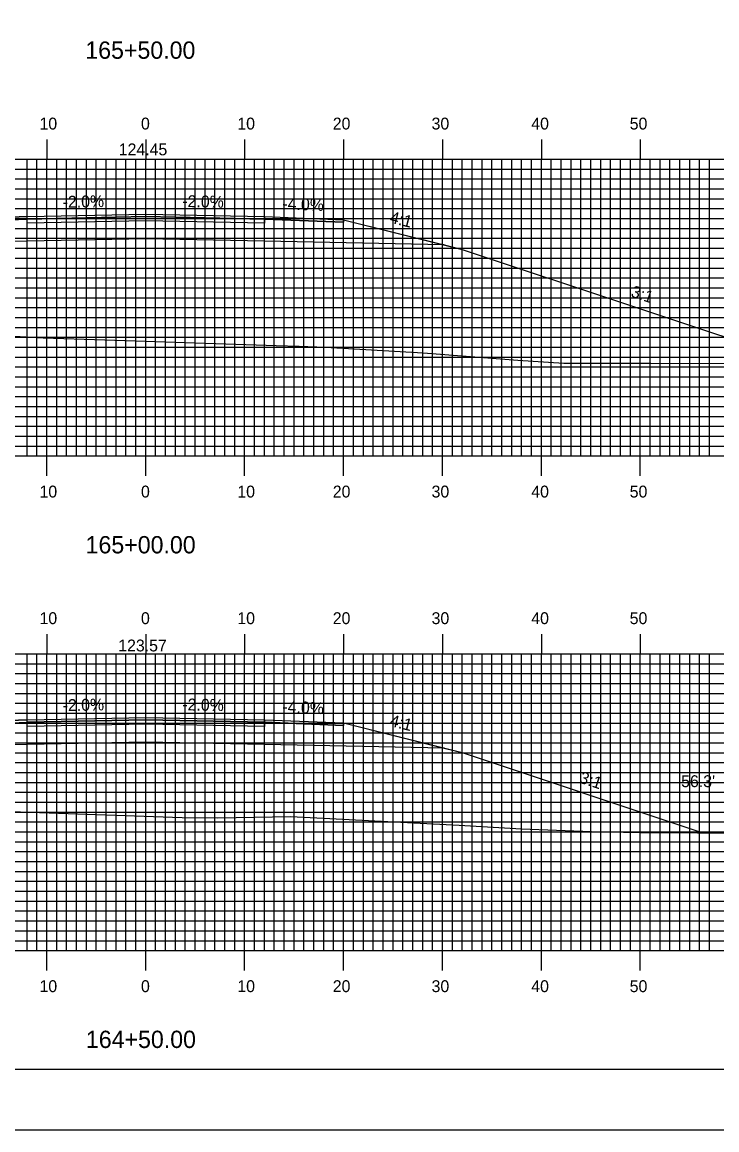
# Model space of a CAD drawing. Extents: x 1781073 to 1781416, y 442591 to 442811.
# Drawn here: x 1781226.4 to 1781296.6, y 442590.5 to 442702.5 of the extents above; entities that cross this region are included whole.
import ezdxf

# ---------------------------------------------------------------- set-up
doc = ezdxf.new("R2010")
doc.units = 0
for name, color, linetype in [('ANNOTATION', 7, 'Continuous'), ('BORDER', 7, 'Continuous'), ('D_Roadway_Centerline', 7, 'Continuous'), ('D_Roadway_Centerline_Text', 7, 'Continuous'), ('D_Roadway_Edge_Shoulder', 7, 'Continuous'), ('D_Roadway_Edge_TW', 7, 'Continuous'), ('D_Roadway_Pavement', 7, 'Continuous'), ('D_Roadway_SlopeLines', 7, 'Continuous'), ('D_Roadway_SubGrade', 7, 'Continuous'), ('D_Text_Standard', 7, 'Continuous'), ('H_V ANNOTATION', 7, 'Continuous'), ('MAJOR', 7, 'Continuous'), ('MINOR', 7, 'Continuous'), ('PLOT BOUNDARY', 7, 'Continuous'), ('S_Roadway_Centerline', 7, 'Continuous')]:
    doc.layers.add(name, color=color, linetype=linetype)

msp = doc.modelspace()

# ---------------------------------------------------------------- linework, layer by layer
at = {"layer": 'BORDER'}
msp.add_lwpolyline([(1781089.29, 442596.67), (1781409.29, 442596.67), (1781409.29, 442806.67), (1781089.29, 442806.67)], close=True, dxfattribs=at)
at = {"layer": 'D_Roadway_Centerline'}
for points in [[(1781185.99, 442672.58), (1781206.89, 442679.55), (1781208.72, 442680.01), (1781218.89, 442682.55), (1781226.89, 442682.87), (1781238.89, 442683.11), (1781250.89, 442682.87), (1781258.89, 442682.55), (1781269.07, 442680.01), (1781270.89, 442679.55), (1781305.63, 442667.98)], [(1781190.49, 442624.58), (1781206.89, 442628.68), (1781208.72, 442629.13), (1781218.89, 442631.68), (1781226.89, 442632), (1781238.89, 442632.24), (1781250.89, 442632), (1781258.89, 442631.68), (1781269.07, 442629.13), (1781270.89, 442628.68), (1781295.21, 442620.57)]]:
    msp.add_lwpolyline(points, dxfattribs=at)
at = {"layer": 'D_Roadway_Edge_Shoulder'}
for points in [[(1781226.89, 442682.87), (1781218.89, 442682.55), (1781218.89, 442682.3), (1781226.89, 442682.62)], [(1781250.89, 442682.87), (1781258.89, 442682.55), (1781258.89, 442682.3), (1781250.89, 442682.62)], [(1781226.89, 442632), (1781218.89, 442631.68), (1781218.89, 442631.43), (1781226.89, 442631.75)], [(1781250.89, 442632), (1781258.89, 442631.68), (1781258.89, 442631.43), (1781250.89, 442631.75)]]:
    msp.add_lwpolyline(points, close=True, dxfattribs=at)
at = {"layer": 'D_Roadway_Edge_TW'}
for points in [[(1781226.89, 442682.62), (1781226.89, 442682.87), (1781238.89, 442683.11), (1781250.89, 442682.87), (1781250.89, 442682.62), (1781238.89, 442682.86)], [(1781226.89, 442631.75), (1781226.89, 442632), (1781238.89, 442632.24), (1781250.89, 442632), (1781250.89, 442631.75), (1781238.89, 442631.99)]]:
    msp.add_lwpolyline(points, close=True, dxfattribs=at)
at = {"layer": 'D_Roadway_Pavement'}
for points in [[(1781226.89, 442682.21), (1781226.89, 442682.62), (1781238.89, 442682.86), (1781250.89, 442682.62), (1781250.89, 442682.21), (1781238.89, 442682.45)], [(1781226.89, 442631.33), (1781226.89, 442631.75), (1781238.89, 442631.99), (1781250.89, 442631.75), (1781250.89, 442631.33), (1781238.89, 442631.57)]]:
    msp.add_lwpolyline(points, close=True, dxfattribs=at)
at = {"layer": 'D_Roadway_SlopeLines'}
for points in [[(1781258.89, 442682.55), (1781270.89, 442679.55), (1781305.63, 442667.98)], [(1781258.89, 442631.68), (1781270.89, 442628.68), (1781295.21, 442620.57)]]:
    msp.add_lwpolyline(points, dxfattribs=at)
at = {"layer": 'D_Roadway_SubGrade'}
for points in [[(1781226.89, 442680.37), (1781208.72, 442680.01), (1781218.89, 442682.55), (1781218.89, 442682.3), (1781226.89, 442682.62), (1781238.89, 442682.86), (1781250.89, 442682.62), (1781258.89, 442682.3), (1781258.89, 442682.55), (1781269.07, 442680.01), (1781250.89, 442680.37), (1781238.89, 442680.61)], [(1781226.89, 442629.5), (1781208.72, 442629.13), (1781218.89, 442631.68), (1781218.89, 442631.43), (1781226.89, 442631.75), (1781238.89, 442631.99), (1781250.89, 442631.75), (1781258.89, 442631.43), (1781258.89, 442631.68), (1781269.07, 442629.13), (1781250.89, 442629.5), (1781238.89, 442629.74)]]:
    msp.add_lwpolyline(points, close=True, dxfattribs=at)
at = {"layer": 'MAJOR'}
for p, q in [((1781228.89, 442690.67), (1781228.89, 442688.67)), ((1781238.89, 442690.67), (1781238.89, 442688.67)), ((1781248.89, 442690.67), (1781248.89, 442688.67)), ((1781258.89, 442690.67), (1781258.89, 442688.67)), ((1781268.89, 442690.67), (1781268.89, 442688.67)), ((1781278.89, 442690.67), (1781278.89, 442688.67)), ((1781288.89, 442690.67), (1781288.89, 442688.67)), ((1781098.89, 442688.67), (1781378.89, 442688.67)), ((1781098.89, 442688.67), (1781378.89, 442688.67)), ((1781228.89, 442658.67), (1781228.89, 442688.67)), ((1781238.89, 442658.67), (1781238.89, 442688.67)), ((1781248.89, 442658.67), (1781248.89, 442688.67)), ((1781258.89, 442658.67), (1781258.89, 442688.67)), ((1781268.89, 442658.67), (1781268.89, 442688.67)), ((1781278.89, 442658.67), (1781278.89, 442688.67)), ((1781288.89, 442658.67), (1781288.89, 442688.67)), ((1781098.89, 442683.67), (1781378.89, 442683.67)), ((1781098.89, 442678.67), (1781378.89, 442678.67)), ((1781098.89, 442673.67), (1781378.89, 442673.67)), ((1781098.89, 442668.67), (1781378.89, 442668.67)), ((1781098.89, 442663.67), (1781378.89, 442663.67)), ((1781098.89, 442658.67), (1781378.89, 442658.67)), ((1781098.89, 442658.67), (1781378.89, 442658.67)), ((1781228.89, 442656.66), (1781228.89, 442658.67)), ((1781238.89, 442656.66), (1781238.89, 442658.67)), ((1781248.89, 442656.66), (1781248.89, 442658.67)), ((1781258.89, 442656.66), (1781258.89, 442658.67)), ((1781268.89, 442656.66), (1781268.89, 442658.67)), ((1781278.89, 442656.66), (1781278.89, 442658.67)), ((1781288.89, 442656.66), (1781288.89, 442658.67)), ((1781228.89, 442640.67), (1781228.89, 442638.67)), ((1781238.89, 442640.67), (1781238.89, 442638.67)), ((1781248.89, 442640.67), (1781248.89, 442638.67)), ((1781258.89, 442640.67), (1781258.89, 442638.67)), ((1781268.89, 442640.67), (1781268.89, 442638.67)), ((1781278.89, 442640.67), (1781278.89, 442638.67)), ((1781288.89, 442640.67), (1781288.89, 442638.67)), ((1781098.89, 442638.67), (1781378.89, 442638.67)), ((1781098.89, 442638.67), (1781378.89, 442638.67)), ((1781228.89, 442608.67), (1781228.89, 442638.67)), ((1781238.89, 442608.67), (1781238.89, 442638.67)), ((1781248.89, 442608.67), (1781248.89, 442638.67)), ((1781258.89, 442608.67), (1781258.89, 442638.67)), ((1781268.89, 442608.67), (1781268.89, 442638.67)), ((1781278.89, 442608.67), (1781278.89, 442638.67)), ((1781288.89, 442608.67), (1781288.89, 442638.67)), ((1781098.89, 442633.67), (1781378.89, 442633.67)), ((1781098.89, 442628.67), (1781378.89, 442628.67)), ((1781098.89, 442623.67), (1781378.89, 442623.67)), ((1781098.89, 442618.67), (1781378.89, 442618.67)), ((1781098.89, 442613.67), (1781378.89, 442613.67)), ((1781098.89, 442608.67), (1781378.89, 442608.67)), ((1781098.89, 442608.67), (1781378.89, 442608.67)), ((1781228.89, 442606.66), (1781228.89, 442608.67)), ((1781238.89, 442606.66), (1781238.89, 442608.67)), ((1781248.89, 442606.66), (1781248.89, 442608.67)), ((1781258.89, 442606.66), (1781258.89, 442608.67)), ((1781268.89, 442606.66), (1781268.89, 442608.67)), ((1781278.89, 442606.66), (1781278.89, 442608.67)), ((1781288.89, 442606.66), (1781288.89, 442608.67))]:
    msp.add_line(p, q, dxfattribs=at)
at = {"layer": 'MINOR'}
for p, q in [((1781226.89, 442658.67), (1781226.89, 442688.67)), ((1781227.89, 442658.67), (1781227.89, 442688.67)), ((1781229.89, 442658.67), (1781229.89, 442688.67)), ((1781230.89, 442658.67), (1781230.89, 442688.67)), ((1781231.89, 442658.67), (1781231.89, 442688.67)), ((1781232.89, 442658.67), (1781232.89, 442688.67)), ((1781233.89, 442658.67), (1781233.89, 442688.67)), ((1781234.89, 442658.67), (1781234.89, 442688.67)), ((1781235.89, 442658.67), (1781235.89, 442688.67)), ((1781236.89, 442658.67), (1781236.89, 442688.67)), ((1781237.89, 442658.67), (1781237.89, 442688.67)), ((1781239.89, 442658.67), (1781239.89, 442688.67)), ((1781240.89, 442658.67), (1781240.89, 442688.67)), ((1781241.89, 442658.67), (1781241.89, 442688.67)), ((1781242.89, 442658.67), (1781242.89, 442688.67)), ((1781243.89, 442658.67), (1781243.89, 442688.67)), ((1781244.89, 442658.67), (1781244.89, 442688.67)), ((1781245.89, 442658.67), (1781245.89, 442688.67)), ((1781246.89, 442658.67), (1781246.89, 442688.67)), ((1781247.89, 442658.67), (1781247.89, 442688.67)), ((1781249.89, 442658.67), (1781249.89, 442688.67)), ((1781250.89, 442658.67), (1781250.89, 442688.67)), ((1781251.89, 442658.67), (1781251.89, 442688.67)), ((1781252.89, 442658.67), (1781252.89, 442688.67)), ((1781253.89, 442658.67), (1781253.89, 442688.67)), ((1781254.89, 442658.67), (1781254.89, 442688.67)), ((1781255.89, 442658.67), (1781255.89, 442688.67)), ((1781256.89, 442658.67), (1781256.89, 442688.67)), ((1781257.89, 442658.67), (1781257.89, 442688.67)), ((1781259.89, 442658.67), (1781259.89, 442688.67)), ((1781260.89, 442658.67), (1781260.89, 442688.67)), ((1781261.89, 442658.67), (1781261.89, 442688.67)), ((1781262.89, 442658.67), (1781262.89, 442688.67)), ((1781263.89, 442658.67), (1781263.89, 442688.67)), ((1781264.89, 442658.67), (1781264.89, 442688.67)), ((1781265.89, 442658.67), (1781265.89, 442688.67)), ((1781266.89, 442658.67), (1781266.89, 442688.67)), ((1781267.89, 442658.67), (1781267.89, 442688.67)), ((1781269.89, 442658.67), (1781269.89, 442688.67)), ((1781270.89, 442658.67), (1781270.89, 442688.67)), ((1781271.89, 442658.67), (1781271.89, 442688.67)), ((1781272.89, 442658.67), (1781272.89, 442688.67)), ((1781273.89, 442658.67), (1781273.89, 442688.67)), ((1781274.89, 442658.67), (1781274.89, 442688.67)), ((1781275.89, 442658.67), (1781275.89, 442688.67)), ((1781276.89, 442658.67), (1781276.89, 442688.67)), ((1781277.89, 442658.67), (1781277.89, 442688.67)), ((1781279.89, 442658.67), (1781279.89, 442688.67)), ((1781280.89, 442658.67), (1781280.89, 442688.67)), ((1781281.89, 442658.67), (1781281.89, 442688.67)), ((1781282.89, 442658.67), (1781282.89, 442688.67)), ((1781283.89, 442658.67), (1781283.89, 442688.67)), ((1781284.89, 442658.67), (1781284.89, 442688.67)), ((1781285.89, 442658.67), (1781285.89, 442688.67)), ((1781286.89, 442658.67), (1781286.89, 442688.67)), ((1781287.89, 442658.67), (1781287.89, 442688.67)), ((1781289.89, 442658.67), (1781289.89, 442688.67)), ((1781290.89, 442658.67), (1781290.89, 442688.67)), ((1781291.89, 442658.67), (1781291.89, 442688.67)), ((1781292.89, 442658.67), (1781292.89, 442688.67)), ((1781293.89, 442658.67), (1781293.89, 442688.67)), ((1781294.89, 442658.67), (1781294.89, 442688.67)), ((1781295.89, 442658.67), (1781295.89, 442688.67)), ((1781098.89, 442687.67), (1781378.89, 442687.67)), ((1781098.89, 442686.67), (1781378.89, 442686.67)), ((1781098.89, 442685.67), (1781378.89, 442685.67)), ((1781098.89, 442684.67), (1781378.89, 442684.67)), ((1781098.89, 442682.67), (1781378.89, 442682.67)), ((1781098.89, 442681.67), (1781378.89, 442681.67)), ((1781098.89, 442680.67), (1781378.89, 442680.67)), ((1781098.89, 442679.67), (1781378.89, 442679.67)), ((1781098.89, 442677.67), (1781378.89, 442677.67)), ((1781098.89, 442676.67), (1781378.89, 442676.67)), ((1781098.89, 442675.67), (1781378.89, 442675.67)), ((1781098.89, 442674.67), (1781378.89, 442674.67)), ((1781098.89, 442672.67), (1781378.89, 442672.67)), ((1781098.89, 442671.67), (1781378.89, 442671.67)), ((1781098.89, 442670.67), (1781378.89, 442670.67)), ((1781098.89, 442669.67), (1781378.89, 442669.67)), ((1781098.89, 442667.67), (1781378.89, 442667.67)), ((1781098.89, 442666.67), (1781378.89, 442666.67)), ((1781098.89, 442665.67), (1781378.89, 442665.67)), ((1781098.89, 442664.67), (1781378.89, 442664.67)), ((1781098.89, 442662.67), (1781378.89, 442662.67)), ((1781098.89, 442661.67), (1781378.89, 442661.67)), ((1781098.89, 442660.67), (1781378.89, 442660.67)), ((1781098.89, 442659.67), (1781378.89, 442659.67)), ((1781226.89, 442608.67), (1781226.89, 442638.67)), ((1781227.89, 442608.67), (1781227.89, 442638.67)), ((1781229.89, 442608.67), (1781229.89, 442638.67)), ((1781230.89, 442608.67), (1781230.89, 442638.67)), ((1781231.89, 442608.67), (1781231.89, 442638.67)), ((1781232.89, 442608.67), (1781232.89, 442638.67)), ((1781233.89, 442608.67), (1781233.89, 442638.67)), ((1781234.89, 442608.67), (1781234.89, 442638.67)), ((1781235.89, 442608.67), (1781235.89, 442638.67)), ((1781236.89, 442608.67), (1781236.89, 442638.67)), ((1781237.89, 442608.67), (1781237.89, 442638.67)), ((1781239.89, 442608.67), (1781239.89, 442638.67)), ((1781240.89, 442608.67), (1781240.89, 442638.67)), ((1781241.89, 442608.67), (1781241.89, 442638.67)), ((1781242.89, 442608.67), (1781242.89, 442638.67)), ((1781243.89, 442608.67), (1781243.89, 442638.67)), ((1781244.89, 442608.67), (1781244.89, 442638.67)), ((1781245.89, 442608.67), (1781245.89, 442638.67)), ((1781246.89, 442608.67), (1781246.89, 442638.67)), ((1781247.89, 442608.67), (1781247.89, 442638.67)), ((1781249.89, 442608.67), (1781249.89, 442638.67)), ((1781250.89, 442608.67), (1781250.89, 442638.67)), ((1781251.89, 442608.67), (1781251.89, 442638.67)), ((1781252.89, 442608.67), (1781252.89, 442638.67)), ((1781253.89, 442608.67), (1781253.89, 442638.67)), ((1781254.89, 442608.67), (1781254.89, 442638.67)), ((1781255.89, 442608.67), (1781255.89, 442638.67)), ((1781256.89, 442608.67), (1781256.89, 442638.67)), ((1781257.89, 442608.67), (1781257.89, 442638.67)), ((1781259.89, 442608.67), (1781259.89, 442638.67)), ((1781260.89, 442608.67), (1781260.89, 442638.67)), ((1781261.89, 442608.67), (1781261.89, 442638.67)), ((1781262.89, 442608.67), (1781262.89, 442638.67)), ((1781263.89, 442608.67), (1781263.89, 442638.67)), ((1781264.89, 442608.67), (1781264.89, 442638.67)), ((1781265.89, 442608.67), (1781265.89, 442638.67)), ((1781266.89, 442608.67), (1781266.89, 442638.67)), ((1781267.89, 442608.67), (1781267.89, 442638.67)), ((1781269.89, 442608.67), (1781269.89, 442638.67)), ((1781270.89, 442608.67), (1781270.89, 442638.67)), ((1781271.89, 442608.67), (1781271.89, 442638.67)), ((1781272.89, 442608.67), (1781272.89, 442638.67)), ((1781273.89, 442608.67), (1781273.89, 442638.67)), ((1781274.89, 442608.67), (1781274.89, 442638.67)), ((1781275.89, 442608.67), (1781275.89, 442638.67)), ((1781276.89, 442608.67), (1781276.89, 442638.67)), ((1781277.89, 442608.67), (1781277.89, 442638.67)), ((1781279.89, 442608.67), (1781279.89, 442638.67)), ((1781280.89, 442608.67), (1781280.89, 442638.67)), ((1781281.89, 442608.67), (1781281.89, 442638.67)), ((1781282.89, 442608.67), (1781282.89, 442638.67)), ((1781283.89, 442608.67), (1781283.89, 442638.67)), ((1781284.89, 442608.67), (1781284.89, 442638.67)), ((1781285.89, 442608.67), (1781285.89, 442638.67)), ((1781286.89, 442608.67), (1781286.89, 442638.67)), ((1781287.89, 442608.67), (1781287.89, 442638.67)), ((1781289.89, 442608.67), (1781289.89, 442638.67)), ((1781290.89, 442608.67), (1781290.89, 442638.67)), ((1781291.89, 442608.67), (1781291.89, 442638.67)), ((1781292.89, 442608.67), (1781292.89, 442638.67)), ((1781293.89, 442608.67), (1781293.89, 442638.67)), ((1781294.89, 442608.67), (1781294.89, 442638.67)), ((1781295.89, 442608.67), (1781295.89, 442638.67)), ((1781098.89, 442637.67), (1781378.89, 442637.67)), ((1781098.89, 442636.67), (1781378.89, 442636.67)), ((1781098.89, 442635.67), (1781378.89, 442635.67)), ((1781098.89, 442634.67), (1781378.89, 442634.67)), ((1781098.89, 442632.67), (1781378.89, 442632.67)), ((1781098.89, 442631.67), (1781378.89, 442631.67)), ((1781098.89, 442630.67), (1781378.89, 442630.67)), ((1781098.89, 442629.67), (1781378.89, 442629.67)), ((1781098.89, 442627.67), (1781378.89, 442627.67)), ((1781098.89, 442626.67), (1781378.89, 442626.67)), ((1781098.89, 442625.67), (1781378.89, 442625.67)), ((1781098.89, 442624.67), (1781378.89, 442624.67)), ((1781098.89, 442622.67), (1781378.89, 442622.67)), ((1781098.89, 442621.67), (1781378.89, 442621.67)), ((1781098.89, 442620.67), (1781378.89, 442620.67)), ((1781098.89, 442619.67), (1781378.89, 442619.67)), ((1781098.89, 442617.67), (1781378.89, 442617.67)), ((1781098.89, 442616.67), (1781378.89, 442616.67)), ((1781098.89, 442615.67), (1781378.89, 442615.67)), ((1781098.89, 442614.67), (1781378.89, 442614.67)), ((1781098.89, 442612.67), (1781378.89, 442612.67)), ((1781098.89, 442611.67), (1781378.89, 442611.67)), ((1781098.89, 442610.67), (1781378.89, 442610.67)), ((1781098.89, 442609.67), (1781378.89, 442609.67))]:
    msp.add_line(p, q, dxfattribs=at)
at = {"layer": 'PLOT BOUNDARY'}
msp.add_lwpolyline([(1781073.11, 442590.55), (1781413.11, 442590.55), (1781413.11, 442810.55), (1781073.11, 442810.55)], close=True, dxfattribs=at)
at = {"layer": 'S_Roadway_Centerline'}
for points in [[(1781174.3, 442673.36), (1781181.76, 442672.85), (1781190.68, 442672.29), (1781197.53, 442671.96), (1781204.7, 442671.85), (1781213.28, 442671.48), (1781228.52, 442670.62), (1781234.75, 442670.42), (1781252.07, 442669.85), (1781254.41, 442669.78), (1781257.06, 442669.67), (1781266.95, 442669.1), (1781276.5, 442668.37), (1781281.17, 442668.06), (1781289.95, 442668.04), (1781299.54, 442668.01)], [(1781172.63, 442624.6), (1781192.65, 442624.57), (1781196.54, 442624.41), (1781200.59, 442624.11), (1781215.65, 442623.03), (1781219.28, 442622.97), (1781224.31, 442622.75), (1781242.58, 442622.12), (1781246.18, 442622.1), (1781253.57, 442622.22), (1781270.57, 442621.33), (1781276.87, 442620.98), (1781283.97, 442620.7), (1781288.82, 442620.61), (1781294.69, 442620.58), (1781301.58, 442620.54)]]:
    msp.add_lwpolyline(points, dxfattribs=at)

# ---------------------------------------------------------------- texts
at = {"layer": 'ANNOTATION'}
for s, rotation, p in [('-2.0%', 1.1458, (1781230.5, 442683.75)), ('-2.0%', 358.8542, (1781242.58, 442683.84)), ('-4.0%', 357.7094, (1781252.69, 442683.6)), ('4:1', 345.9638, (1781263.49, 442682.27)), ('3:1', 341.5652, (1781287.86, 442674.8)), ('-2.0%', 1.1458, (1781230.5, 442632.87)), ('-2.0%', 358.8542, (1781242.58, 442632.96)), ('-4.0%', 357.7094, (1781252.69, 442632.73)), ('4:1', 345.9638, (1781263.49, 442631.39)), ('3:1', 341.5652, (1781282.65, 442625.67))]:
    msp.add_text(s, height=1.2, rotation=rotation, dxfattribs=at).set_placement(p)
at = {"layer": 'D_Roadway_Centerline'}
for s, p in [('C', (1781238.89, 442683.11)), ('L', (1781238.89, 442683.11)), ('C', (1781238.89, 442632.24)), ('L', (1781238.89, 442632.23))]:
    msp.add_text(s, height=0.0146, dxfattribs=at).set_placement(p)
at = {"layer": 'D_Roadway_Centerline_Text'}
for s, p in [('124.45', (1781236.16, 442689.06)), ('123.57', (1781236.11, 442638.91))]:
    msp.add_text(s, height=1.2, dxfattribs=at).set_placement(p)
at = {"layer": 'D_Text_Standard'}
msp.add_text("56.3'", height=1.2, dxfattribs=at).set_placement((1781293.02, 442625.19))
at = {"layer": 'H_V ANNOTATION'}
for s, height, p in [('165+50.00', 1.75, (1781232.78, 442698.82)), ('10', 1.2, (1781228.15, 442691.67)), ('0', 1.2, (1781238.41, 442691.67)), ('10', 1.2, (1781248.15, 442691.67)), ('20', 1.2, (1781257.8, 442691.67)), ('30', 1.2, (1781267.79, 442691.67)), ('40', 1.2, (1781277.87, 442691.67)), ('50', 1.2, (1781287.82, 442691.67)), ('10', 1.2, (1781228.15, 442654.47)), ('0', 1.2, (1781238.41, 442654.47)), ('10', 1.2, (1781248.15, 442654.47)), ('20', 1.2, (1781257.8, 442654.47)), ('30', 1.2, (1781267.79, 442654.47)), ('40', 1.2, (1781277.87, 442654.47)), ('50', 1.2, (1781287.82, 442654.47)), ('165+00.00', 1.75, (1781232.81, 442648.82)), ('10', 1.2, (1781228.15, 442641.67)), ('0', 1.2, (1781238.41, 442641.67)), ('10', 1.2, (1781248.15, 442641.67)), ('20', 1.2, (1781257.8, 442641.67)), ('30', 1.2, (1781267.79, 442641.67)), ('40', 1.2, (1781277.87, 442641.67)), ('50', 1.2, (1781287.82, 442641.67)), ('10', 1.2, (1781228.15, 442604.47)), ('0', 1.2, (1781238.41, 442604.47)), ('10', 1.2, (1781248.15, 442604.47)), ('20', 1.2, (1781257.8, 442604.47)), ('30', 1.2, (1781267.79, 442604.47)), ('40', 1.2, (1781277.87, 442604.47)), ('50', 1.2, (1781287.82, 442604.47)), ('164+50.00', 1.75, (1781232.84, 442598.82))]:
    msp.add_text(s, height=height, dxfattribs=at).set_placement(p)

doc.saveas('drawing.dxf')
